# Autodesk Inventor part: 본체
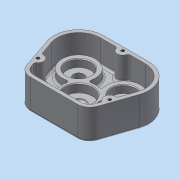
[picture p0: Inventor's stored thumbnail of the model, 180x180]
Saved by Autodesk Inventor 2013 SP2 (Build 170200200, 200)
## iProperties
Created: 2014-12
Part Number: 본체
Material: 알루미늄 6061
Document SubType Name: Modeling
Designer: dgall
Density: 2.71 g/cm^3
Mass: 612.573 g
Surface Area: 666.928 cm^2
Volume: 226.042 cm^3
Author: dgall
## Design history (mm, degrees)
sketch "스케치1"
  geometry: L1 (-47, 36)-(47, 36); L2 (0, 0)-(-32.527, -32.527); L3 (0, 0)-(32.527, -32.527); L4 (-32.527, -68.527)-(32.527, -68.527); L5 (-47, 36)-(-66.565, -20.803); L6 (47, 36)-(66.565, -20.803); A1 r 46 centre (0, 0) between (-32.527, -32.527) and (32.527, -32.527); A2 r 36 centre (-32.527, -32.527) between (-66.565, -20.803) and (-32.527, -68.527); A3 r 36 centre (32.527, -32.527) between (32.527, -68.527) and (66.565, -20.803); 2 further points
  constraints: 12 end point, 6 point on circle, 4 tangent, 3 centre point, 3 coincident, 1 horizontal, 1 horizontal alignment, 1 midpoint, 1 parallel, 1 vertical alignment
  dimensions: "d0" = 46 radius of A1; "d2" = 36 distance from line of point (0, 0) L1; "d3" = 94 distance of L1.start L1.end; "d4" = 90 deg angle of L3 L2; "d5" = 36 radius of A2
extrude "돌출1" new body sketch "스케치1" distance "d6" = 44; taper "d7" = 0 deg
fillet "모깎기9" dims "d87" = 18
sketch "스케치2"
  geometry: L1 (32.527, 68.527)-(-32.527, 68.527) reference; L2 (-32.527, 63.527)-(32.527, 63.527); L3 (61.837, 22.432)-(46.453, -22.233); L4 (34.162, -31)-(-34.162, -31); L5 (-46.453, -22.233)-(-61.837, 22.432); A1 r 36 centre (32.527, 32.527) between (66.565, 20.803) and (32.527, 68.527) reference; A2 r 36 centre (-32.527, 32.527) between (-32.527, 68.527) and (-66.565, 20.803) reference; A3 r 18 centre (34.162, -18) between (34.162, -36) and (51.181, -23.862) reference; A4 r 18 centre (-34.162, -18) between (-51.181, -23.862) and (-34.162, -36) reference; A5 r 13 centre (-34.162, -18) between (-46.453, -22.233) and (-34.162, -31); A6 r 13 centre (34.162, -18) between (34.162, -31) and (46.453, -22.233); A7 r 31 centre (32.527, 32.527) between (61.837, 22.432) and (32.527, 63.527); A8 r 31 centre (-32.527, 32.527) between (-32.527, 63.527) and (-61.837, 22.432); 1 further point
  constraints: 8 end point, 8 point on circle, 5 tangent, 4 centre point, 1 equal length, 1 equal radius, 1 other
  dimensions: "d88" = 5 distance between parallel lines of L2 L1; "d89" = 5 radial gap between concentric circles of A5 A4; "d90" = 5 radial gap between concentric circles of A3 A6
extrude "돌출2" cut sketch "스케치2" distance "d9" = 34; taper "d10" = 0 deg
sketch "스케치3"
  geometry: A1 r 24 centre (32.527, 32.527) between (21.111, 11.416) and (11.416, 21.111); A2 r 24 centre (-32.527, 32.527) between (-11.416, 21.111) and (-21.111, 11.416); A3 r 24 centre (0, 0) between (11.416, 21.111) and (-11.416, 21.111); A4 r 24 centre (0, 0) between (-21.111, 11.416) and (21.111, 11.416); A5 r 36 centre (-32.527, 32.527) between (-32.527, 68.527) and (-66.565, 20.803) reference; A6 r 36 centre (32.527, 32.527) between (66.565, 20.803) and (32.527, 68.527) reference; 1 further point
  constraints: 8 point on circle, 4 centre point, 3 coincident
  dimensions: "d13" = 48 diameter of A1; "d14" = 48 diameter of A2; "d16" = 48 diameter of A4; "d17" = 48 diameter of A3 (= d16)
extrude "돌출3" join sketch "스케치3" distance "d18" = 11; taper "d19" = 0 deg
hole "구멍1" diameter "d22" = 20; stored, may be unused: countersink angle "d26" = 90 deg, drill point angle "d28" = 0 deg; dims "d20" = 10, "d21" = 10, "d23" = 6, "d24" = 40, "d25" = 12, "d27" = 15
sketch "스케치4"
  geometry: C1 r 20 at (-32.527, -32.527); A1 r 36 centre (-32.527, -32.527) between (-66.565, -20.803) and (-32.527, -68.527) reference; 1 further point
  constraints: 1 centre point, 1 coincident
  dimensions: "d29" = 40 diameter of C1
extrude "돌출4" join sketch "스케치4" distance "d31" = 7; taper "d32" = -10 deg
hole "구멍2" diameter "d35" = 30; stored, may be unused: countersink angle "d39" = 90 deg, drill point angle "d41" = 0 deg; dims "d33" = 10, "d34" = 10, "d36" = 6, "d37" = 40, "d38" = 12, "d40" = 7
hole "구멍3" diameter "d44" = 15.5; stored, may be unused: countersink angle "d48" = 90 deg, drill point angle "d50" = 0 deg; dims "d42" = 10, "d43" = 10, "d45" = 6, "d46" = 35, "d47" = 11, "d49" = 21
fillet "모깎기2" dims "d77" = 0.3
fillet "모깎기3" dims "d78" = 0.1
fillet "모깎기4" dims "d79" = 0.3
chamfer "모따기1" distance "d80" = 1; stored, may be unused: second distance "d81" = 2, angle "d82" = 45 deg
fillet "모깎기5" dims "d83" = 3
fillet "모깎기6" dims "d84" = 3
fillet "모깎기7" dims "d85" = 3
sketch "스케치6"
  geometry: L1 (-32.527, 63.527)-(32.527, 63.527) reference; L2 (-46.453, -22.233)-(-61.837, 22.432) reference; L3 (61.837, 22.432)-(46.453, -22.233) reference; L4 (34.162, -36)-(-34.162, -36) reference; A1 r 27 centre (0, 0) between (-26.263, 6.263) and (26.263, 6.263) reference; A2 r 8 centre (51.7, -7) between (54.305, 0.564) and (49.095, -14.564); A3 r 8 centre (-51.7, -7) between (-49.095, -14.564) and (-54.305, 0.564); A4 r 8 centre (0, 63.527) between (-8, 63.527) and (8, 63.527)
  constraints: 8 point on line, 6 point on circle, 3 centre point, 1 equal radius, 1 midpoint, 1 vertical alignment
  dimensions: "d92" = 8 radius of A4; "d94" = 29 distance from line of A3.centre L4; "d95" = 8 radius of A3; "d96" = 29 distance from line of A2.centre L4
extrude "돌출6" join sketch "스케치6" stored distance "d97" = 7; taper "d98" = 0 deg
hole "구멍6" diameter "d101" = 4.459; stored, may be unused: countersink angle "d105" = 90 deg, drill point angle "d107" = 118 deg; dims "d99" = 10, "d100" = 10, "d102" = 20, "d103" = 35, "d104" = 11, "d106" = 23
hole "구멍7" diameter "d110" = 4.459; stored, may be unused: countersink angle "d114" = 90 deg, drill point angle "d116" = 118 deg; dims "d108" = 10, "d109" = 10, "d111" = 20, "d112" = 35, "d113" = 11, "d115" = 23
fillet "모깎기10" dims "d117" = 3
fillet "모깎기11" dims "d118" = 3
fillet "모깎기12" dims "d119" = 3
fillet "모깎기13" dims "d120" = 3
sketch "스케치7"
  geometry: L1 (34.162, 36)-(-34.162, 36) reference; 3 further points
  constraints: 1 coincident, 1 vertical alignment, 1 other
  dimensions: "d121" = 30 distance from line of point (0, 6) L1
feature "엠보싱1" sketch "스케치7" dims "d0" = 46, "d2" = 36, "d3" = 94, "d4" = 90 deg, "d5" = 36, "d122" = 1, "d123" = 0
chamfer "모따기2" distance "d124" = 1; stored, may be unused: second distance "d125" = 2, angle "d126" = 45 deg
fillet "모깎기14" dims "d127" = 3
node "솔리드1"
mirror "대칭1"
mirror "대칭2"
mirror "대칭4"
other parameters: "d11" = 48
